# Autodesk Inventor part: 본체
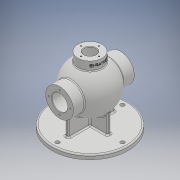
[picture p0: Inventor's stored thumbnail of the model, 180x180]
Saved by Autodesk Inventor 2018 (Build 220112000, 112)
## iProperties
Created: 2020-08
Part Number: 본체
Material: 일반
Document SubType Name: Modeling
Designer: USER
Density: 1 g/cm^3
Appearance: 기본값
Author: USER
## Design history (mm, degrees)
sketch "스케치1"
  geometry: L1 (0, 0)-(201.306, 0); L2 (0, 0)-(0, 31); L3 (136, 31)-(136, 0); L4 (0, 31)-(25.012, 31); L5 (110.988, 31)-(136, 31); L6 (0, 17.5)-(28.722, 17.5); L7 (107.278, 17.5)-(118.25, 17.5); L8 (118.25, 17.5)-(118.25, 18.5); L9 (118.25, 18.5)-(120, 18.5); L10 (120, 18.5)-(120, 17.5); L11 (120, 17.5)-(136, 17.5); A1 r 53 centre (68, 0) between (110.988, 31) and (25.012, 31); A2 r 43 centre (68, 0) between (107.278, 17.5) and (28.722, 17.5)
  constraints: 22 end point, 7 perpendicular, 4 point on circle, 4 point on line, 3 horizontal, 2 centre point, 1 coincident, 1 horizontal alignment, 1 vertical
  dimensions: "d0" = 106 diameter of A1; "d3" = 68 distance of A1.centre L1.start; "d4" = 136 distance between parallel lines of L2 L3; "d5" = 62 diameter of L4 L1; "d6" = 62 diameter of L5 L1; "d7" = 86 diameter of A2; "d88" = 35 diameter of L11 L1; "d89" = 37 diameter of L9 L1; "d90" = 1.75 distance of L8.end L9.end; "d91" = 16 distance of L10.end L11.end; "d92" = 35 diameter of L6 L1
revolve "회전1" sketch "스케치1" stored, may be unused: angle "d14" = 90 deg
node "작업 평면1"
sketch "스케치2"
  geometry: C1 r 27 at (0, 68); 1 further point
  constraints: 1 centre point, 1 vertical alignment
  dimensions: "d16" = 54 diameter of C1; "d17" = 68 distance of point (0, 0) C1.centre
extrude "돌출1" join sketch "스케치2" stored distance "d18" = 10; taper "d19" = 0 deg
sketch "스케치3"
  geometry: C1 r 13 at (0, 0); 1 further point
  constraints: 1 centre point
  dimensions: "d20" = 26 diameter of C1
extrude "돌출2" cut sketch "스케치3" stored distance "d21" = 10; taper "d22" = 0 deg
node "작업 평면2"
sketch "스케치4"
  geometry: C1 r 13 at (0, 68) reference; C2 r 85 at (0, 68); 1 further point
  constraints: 1 centre point, 1 coincident
  dimensions: "d24" = 170 diameter of C2
extrude "돌출3" join sketch "스케치4" distance "d25" = 10; taper "d26" = 0 deg
sketch "스케치5"
  geometry: L1 (-4, -52)-(4, -52); L2 (4, 52)-(-4, 52); L3 (43, -4)-(43, 4); L4 (-43, 4)-(-43, -4); L5 (-4, 52)-(-4, 4); L6 (-4, -4)-(-4, -52); L7 (-43, -4)-(-4, -4); L8 (4, -4)-(43, -4); L9 (43, 4)-(4, 4); L10 (-4, 4)-(-43, 4); L11 (4, -52)-(4, -4); L12 (4, 4)-(4, 52); 4 further points
  constraints: 24 end point, 10 parallel, 4 perpendicular, 3 horizontal, 2 midpoint, 1 horizontal alignment, 1 vertical alignment
  dimensions: "d27" = 8 distance of L4.start L4.end; "d28" = 8 distance of L2.start L2.end; "d29" = 104 distance of L1.end L2.start; "d30" = 86 distance of L3.end L4.start; "d31" = 43 distance from line of L3 point (0, 0); "d32" = 52 distance from line of L1 point (0, 0)
extrude "돌출4" join sketch "스케치5" stored distance "d33" = 10; taper "d34" = 0 deg
sketch "스케치6" dims "d35" = 145
  geometry: 3 further points
  constraints: 1 horizontal alignment, 2 other
hole "구멍1" sketch "스케치6" at (-72.5, 0) diameter "d36" = 9; stored, may be unused: countersink angle "d40" = 90 deg, drill point angle "d42" = 0 deg; dims "d37" = 6, "d38" = 4, "d39" = 2, "d41" = 10
sketch "스케치7" dims "d46" = 48
  geometry: 3 further points
  constraints: 1 coincident, 1 vertical alignment, 2 other
hole "구멍2" sketch "스케치7" at (0, 24) diameter "d47" = 3.242; stored, may be unused: countersink angle "d51" = 90 deg, drill point angle "d53" = 118 deg; dims "d48" = 12, "d49" = 4, "d50" = 2, "d52" = 15
sketch "스케치8" dims "d57" = 48
  geometry: 3 further points
  constraints: 1 coincident, 1 vertical alignment, 2 other
hole "구멍3" sketch "스케치8" at (0, -24) diameter "d58" = 3.242; stored, may be unused: countersink angle "d62" = 90 deg, drill point angle "d64" = 118 deg; dims "d59" = 12, "d60" = 4, "d61" = 2, "d63" = 15
sketch "스케치9" dims "d69" = 40
  geometry: 3 further points
  constraints: 1 horizontal alignment, 2 other
hole "구멍4" sketch "스케치9" at (-20, 0) diameter "d70" = 3.242; stored, may be unused: countersink angle "d74" = 90 deg, drill point angle "d76" = 118 deg; dims "d71" = 12, "d72" = 4, "d73" = 2, "d75" = 15
node "작업 평면3"
sketch "스케치11"
  geometry: L1 (-27, 0)-(27, 0) reference; 2 further points
  constraints: 1 other
  dimensions: "d80" = 9 distance from line of L1 point (0, -9); "d81" = 27 horizontal distance of L1.start point (0, -9)
feature "엠보싱1" sketch "스케치11" dims "d82" = 0.5, "d83" = 0
chamfer "모따기1" distance "d84" = 1; stored, may be unused: second distance "d85" = 2, angle "d86" = 45 deg
fillet "모깎기1" dims "d87" = 3
node "솔리드1"
pattern_circular "원형 패턴1" dims angle "d44" = 360 deg
pattern_circular "원형 패턴2" dims angle "d55" = 360 deg
pattern_circular "원형 패턴3" dims angle "d66" = 360 deg
pattern_circular "원형 패턴4" dims angle "d78" = 360 deg
other parameters: "d2" = 62, "d15" = 65, "d23" = -85
